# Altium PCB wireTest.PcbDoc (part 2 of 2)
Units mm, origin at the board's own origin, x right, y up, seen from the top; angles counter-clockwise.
Board outline 121.22 x 130.26 mm, 2 copper layers (Top Layer, Bottom Layer); 157 components, 144 nets, 513 pads, 186 vias.
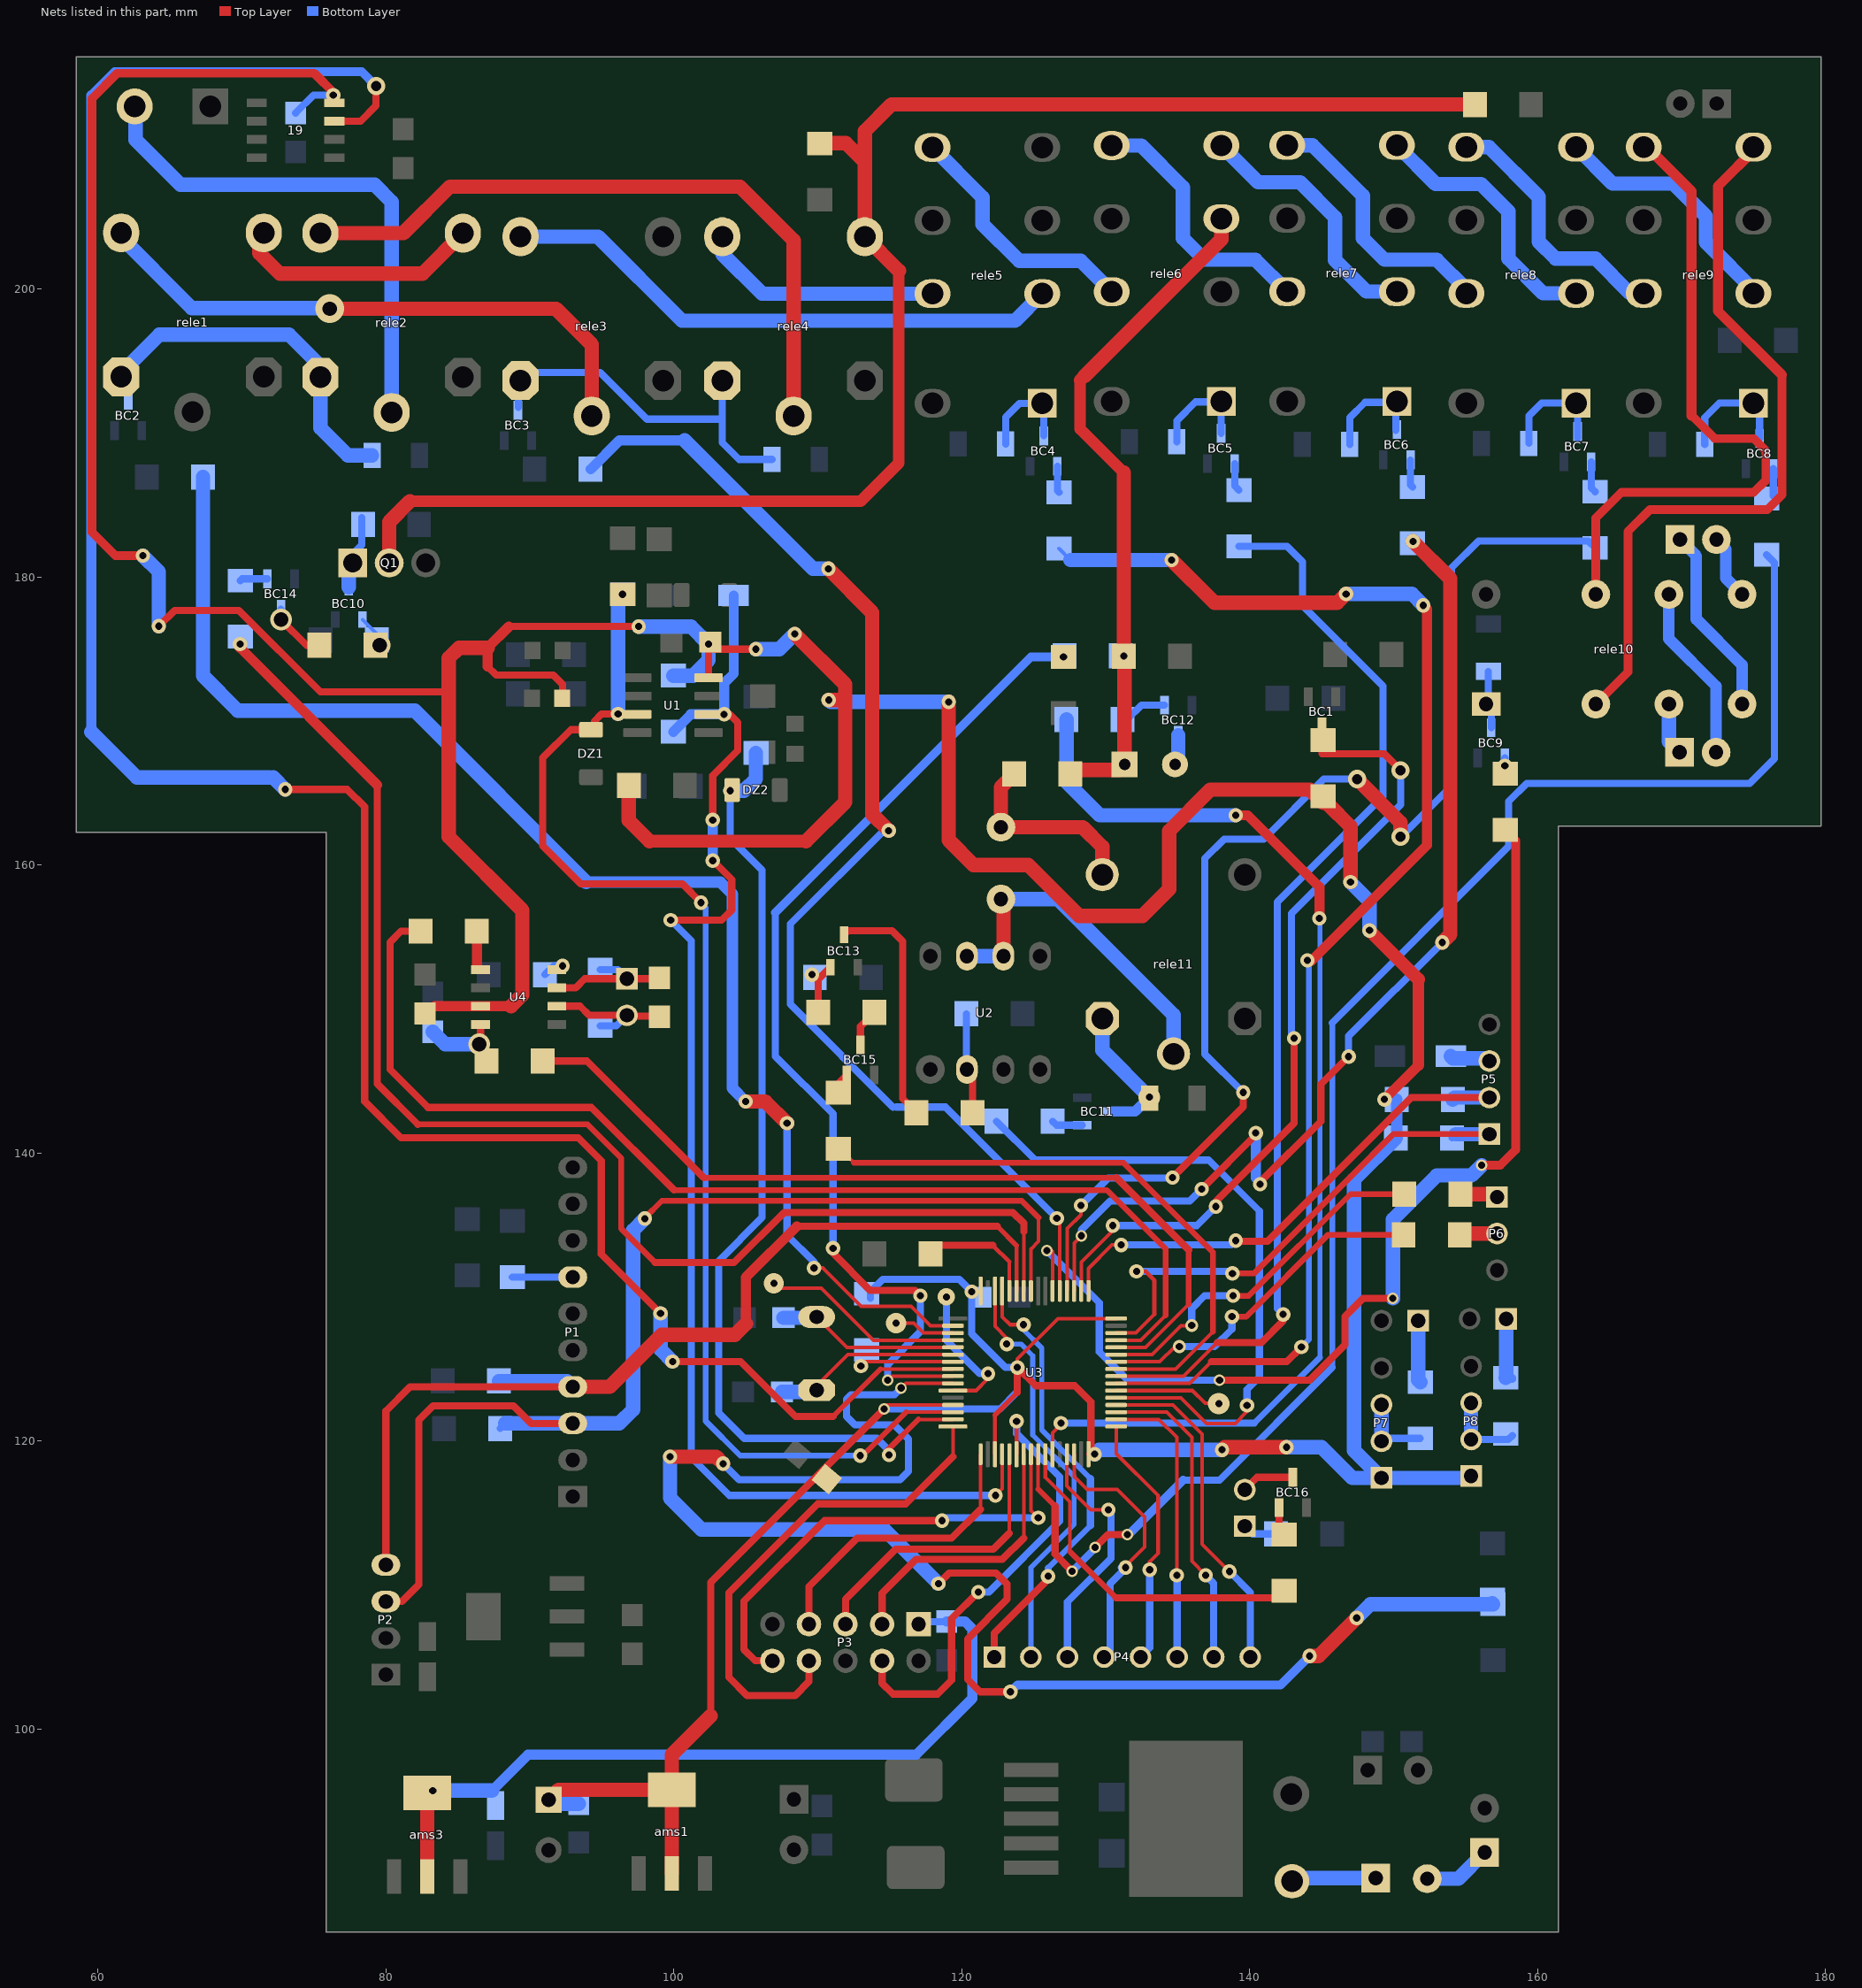
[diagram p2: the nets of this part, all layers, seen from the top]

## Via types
v1: diameter 1, hole 0.5, Top Layer to Bottom Layer, 140 vias
v2: diameter 1.5, hole 1, Top Layer to Bottom Layer, 15 vias
v3: diameter 0.8, hole 0.5, Top Layer to Bottom Layer, 12 vias
v4: diameter 1.27, hole 0.711, Top Layer to Bottom Layer, 6 vias
v5: diameter 2, hole 1, Top Layer to Bottom Layer, 5 vias
v6: diameter 1.5, hole 0.5, Top Layer to Bottom Layer, 3 vias
v7: diameter 1.4, hole 0.5, Top Layer to Bottom Layer, 2 vias
v8: diameter 0.9, hole 0.5, Top Layer to Bottom Layer, 2 vias
v9: diameter 1.2, hole 0.5, Top Layer to Bottom Layer, 1 vias

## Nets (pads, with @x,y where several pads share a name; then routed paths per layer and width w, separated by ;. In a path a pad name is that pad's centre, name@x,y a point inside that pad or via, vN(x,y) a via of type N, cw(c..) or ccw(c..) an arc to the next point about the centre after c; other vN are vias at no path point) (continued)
Net28_1: 28.1 BC4.1 | length 1.9
  Bottom Layer w0.5: BC4.1@126.655,187.697 126.655,185.988 28.1@126.771,185.871
Net29_1: 29.1 BC5.1 | length 2
  Bottom Layer w0.5: BC5.1@138.974,187.875 138.974,186.318 29.1@139.268,186.024
Net30_1: 30.1 BC6.1 | length 1.9
  Bottom Layer w0.5: BC6.1@151.191,188.129 151.191,186.395 30.1@151.333,186.252
Net31_1: 31.1 BC7.1 | length 2.2
  Bottom Layer w0.5: BC7.1@163.739,188.002 163.739,186.191 31.1@164.008,185.922
Net32_1: 32.1 BC8.1 | length 2.2
  Bottom Layer w0.5: BC8.1@176.388,187.52 176.388,185.633 32.1@176.606,185.414
Net33_1: 33.1 BC9.1 | length 0.5
  Bottom Layer w0.5: v1(157.744,166.893) BC9.1@157.744,167.428
Net35_1: 35.1 38.2 BC10.1 | length 2.1
  Top Layer w0.5: 38.2@79.293,175.26 v2(79.578,175.26)
  Bottom Layer w0.25: BC10.1@78.384,177.038 79.369,176.053 35.1@79.369,175.616
Net36_2: 36.2 BC12.1 | length 3.3
  Bottom Layer w0.5: 36.2@131.185,170.104 131.496,170.104 132.495,171.103 BC12.1@134.102,171.103
Net37_1: 37.1 BC11.1 | length 2.2
  Bottom Layer w0.5: 37.1@126.334,142.189 126.598,141.925 BC11.1@128.388,141.925
Net38_1: 38.1 BC14.3 | length 4.1
  Top Layer w0.5: v2(72.72,177.038) 74.498,175.26 38.1@75.393,175.26
  Bottom Layer w0.5: v2(72.72,177.038) BC14.3@72.72,177.766
Net39_1: 39.1 P1.7 | length 4.2
  Bottom Layer w0.5: 39.1@88.798,131.375 92.984,131.375 P1.7@92.989,131.369
Net41_1: 41.1 46.2 BC13.1 | length 3.5
  Top Layer w0.5: 46.2@110.039,149.758 110.039,152.053 BC13.1@110.886,152.901
  other v1: 109.601,152.375
Net42_2: 42.2 48.1 U2.2 | length 7
  Top Layer w0.5: U2.2@120.371,145.798 120.771,145.397 48.1@120.771,142.799
  Bottom Layer w0.5: 42.2@120.326,149.657 120.326,145.843 U2.2@120.371,145.798
Net43_2: 43.2 BC10.3 Q1.1 | length 4.6
  Bottom Layer w0.5: Q1.1@77.699,181.585 78.339,182.225 43.2@78.339,184.125
  Bottom Layer w1: BC10.3@77.434,179.288 77.434,180.711 Q1.1@77.699,180.975
Net45_1: 45.1 BC14.1 | length 1.9
  Bottom Layer w0.5: 45.1@69.901,179.75 70.017,179.866 BC14.1@71.77,179.866
Net46_1: 46.1 BC15.3 | length 2.6
  Top Layer w0.5: BC15.3@112.979,147.506 112.979,148.799 46.1@113.939,149.758
Net47_2: 47.2 BC12.3 | length 2.1
  Bottom Layer w1: 47.2@134.823,166.98 135.052,167.208 BC12.3@135.052,169.003
Net48_2: 48.2 BC13.3 | length 16.8
  Top Layer w0.5: BC13.3@111.836,155.151 112.108,155.423 115.164,155.423 115.9,154.686 115.9,143.77 48.2@116.871,142.799
Net49_2: 49.2 L1.2 rele11.2 | length 13.6
  Top Layer w1: 49.2@123.653,166.319 122.733,165.399 L1.2@122.733,162.622 128.412,162.622 129.775,161.259 rele11.2@129.775,159.327
Net50_1: 50.1 BC15.1 | length 0.9
  Top Layer w0.5: 50.1@111.379,144.756 BC15.1@112.029,145.406
Net53_1: 53.1 ams3.2 ams3.4 C3.1 P3.1 | length 54.8
  Top Layer w1: ams3.2@82.88,89.734 ams3.4@82.88,95.534
  Bottom Layer w0.5: P3.1@117.018,107.264 117.199,107.446 53.1@118.974,107.446
  Bottom Layer w0.7: 87.376,95.707 89.865,98.196 116.84,98.196 120.752,102.108 120.752,106.934 120.24,107.446 53.1@118.974,107.446
  Bottom Layer w1: v1(83.261,95.707) 87.376,95.707
Net54_2: 54.2@156.921,108.655 57.2 U3.10 | length 110.3
  Top Layer w0.25: v3(115.799,123.673) 116.115,123.989 U3.10@119.4,123.989
  Top Layer w0.5: v1(118.389,110.084) 119.126,110.82 122.403,110.82 123.165,110.058 123.165,108.991 120.421,106.248 120.421,103.429 121.285,102.565 v1(123.393,102.565)
  Top Layer w1: v1(99.746,118.897) 102.946,118.897 v1(103.429,118.415) ; v1(144.17,105.054) 144.805,105.054 v1(147.447,107.696)
  Bottom Layer w0.35: v3(115.799,123.673) v3@115.824,123.673
  Bottom Layer w0.5: v1(103.429,118.415) 104.546,117.297 115.722,117.297 116.307,117.881 116.307,120.117 115.316,121.107 112.598,121.107 112.014,121.691 112.014,122.885 112.319,123.19 115.341,123.19 v3@115.824,123.673
  Bottom Layer w0.6: v1(123.393,102.565) 123.876,103.048 142.164,103.048 v1(144.17,105.054)
  Bottom Layer w1: v1(99.746,118.897) 99.746,116.027 101.93,113.843 114.63,113.843 v1(118.389,110.084) ; v1(147.447,107.696) 148.406,108.655 54.2@156.921,108.655 57.2@156.865,108.712
Net55_1: 55.1@113.411,126.32 U3.7 | length 6.7
  Top Layer w0.25: v1(113.005,125.197) 112.928,125.197 113.221,125.489 U3.7@119.4,125.489
Net56_1: 56.1 U3.60 | length 8.2
  Top Layer w0.25: 56.1@117.85,132.994 56.1@118.434,133.579 ; U3.60@123.32,130.409 123.32,132.433
  Top Layer w0.3: 122.174,133.579 123.32,132.433
  Top Layer w0.5: 56.1@118.434,133.579 122.174,133.579
Net60_2: 60.2 U3.5 Y1.2 | length 12.7
  Top Layer w0.25: Y1.2@109.931,128.6 112.042,126.489 U3.5@119.4,126.489
  Bottom Layer w1: 60.2@107.624,128.549 109.88,128.549 Y1.2@109.931,128.6
Net61_2: 61.2 P6.2 | length 2.6
  Top Layer w0.25: 61.2@154.604,134.315 61.2@155.092,134.315
  Top Layer w1: 61.2@155.092,134.315 155.169,134.391 P6.2@157.201,134.391
Net62_2: 62.2 P6.1 | length 2.6
  Top Layer w1: 62.2@154.655,137.135 156.997,137.135 P6.1@157.201,136.931
Net63_1: 63.1 buzzer1.1 | length 2.4
  Bottom Layer w0.5: buzzer1.1@139.67,114.071 140.203,113.538 63.1@141.834,113.538
Net64_2: 64.2 U3.6 Y1.1 | length 13.1
  Top Layer w0.25: Y1.1@109.931,123.52 109.931,123.825 112.096,125.989 U3.6@119.4,125.989
  Bottom Layer w1: 64.2@107.522,123.393 109.804,123.393 Y1.1@109.931,123.52
Net66_1: 66.1 BC16.1 | length 2
  Top Layer w0.5: BC16.1@142.062,115.367 142.062,113.837 66.1@142.418,113.481
Net68_1: 68.1 led1.1 | length 4.3
  Bottom Layer w1: led1.1@151.714,128.346 151.714,124.226 68.1@151.867,124.073
Net68_2: 68.2 P7.2 P7.3 | length 5.3
  Bottom Layer w0.5: P7.2@149.174,119.964 149.383,120.173 68.2@151.867,120.173
  Bottom Layer w1: P7.2@149.174,119.964 P7.3@149.174,122.504
Net69_1: 69.1 led2.1 | length 4.2
  Bottom Layer w0.5: 69.1@158.267,124.276 69.1@158.267,124.378
  Bottom Layer w1: 69.1@157.81,124.378 157.836,124.403 led2.1@157.836,128.473
Net69_2: 69.2 P8.2 P8.3 | length 5.5
  Bottom Layer w0.5: P8.2@155.397,120.091 157.982,120.091 69.2@158.267,120.376
  Bottom Layer w1: P8.2@155.397,120.091 P8.3@155.397,122.631
Net71_1: 71.1 73.1 U4.4 | length 6.3
  Top Layer w0.5: v2(86.487,147.549) 86.487,146.894 73.1@87.001,146.38 ; v2@86.58,147.549 U4.4@86.58,148.92
  Bottom Layer w1: 71.1@83.261,148.408 84.121,147.549 v2(86.487,147.549)
Net72_1: 72.1 U4.1 | length 2.8
  Top Layer w0.5: U4.1@86.329,152.982 U4.1@86.58,152.73
  Top Layer w0.7: U4.1@86.329,152.982 72.1@86.329,155.397
Net74_1: 74.1 75.2 buzzer2.1 U4.7 | length 9.6
  Top Layer w0.5: U4.7@91.88,151.46 93.193,151.46 93.828,152.095 buzzer2.1@96.749,152.095 98.955,152.095 75.2@99.06,152.201
  Bottom Layer w0.5: 74.1@94.894,152.724 96.119,152.724 buzzer2.1@96.749,152.095
Net74_2: 74.2 75.1 buzzer2.2 U4.6 | length 9.6
  Top Layer w0.5: U4.6@91.88,150.19 93.497,150.19 94.132,149.555 buzzer2.2@96.749,149.555 96.803,149.501 75.1@99.06,149.501
  Bottom Layer w0.5: 74.2@94.894,148.824 96.018,148.824 buzzer2.2@96.749,149.555
Net76_1: 76.1 U4.8 | length 1.5
  Bottom Layer w0.5: 76.1@91.053,152.375 91.663,152.984 v1(92.278,152.984)
NetBC2_3: BC2.3 D5.1 rele1.4 rele2.4 | length 25.6
  Bottom Layer w0.5: rele1.4@61.322,193.208 rele1.4@61.322,193.878
  Bottom Layer w1: rele1.4@61.322,193.878 64.268,196.825 73.279,196.825 75.463,194.64 rele2.4@75.463,193.878 75.463,190.348 77.368,188.443 D5.1@79.045,188.443
NetBC3_3: BC3.3 D6.1 rele3.4 rele4.4 | length 25.8
  Bottom Layer w0.5: BC3.3@89.205,191.772 89.205,193.48 rele3.4@89.36,193.636 89.933,194.208 94.894,194.208 98.146,190.957 103.378,190.957 ; rele4.4@103.378,193.632 103.378,189.332 104.546,188.163 D6.1@106.832,188.163
NetBC4_3: BC4.3 D7.1 rele5.1 | length 7.1
  Bottom Layer w0.5: D7.1@123.061,189.23 123.061,191.108 124.011,192.058 rele5.1@125.603,192.058 125.705,191.956 BC4.3@125.705,189.797
NetBC5_3: BC5.3 D8.1 rele6.1 | length 7.3
  Bottom Layer w0.5: D8.1@134.95,189.382 134.95,190.856 136.254,192.159 rele6.1@138.024,192.159 ; BC5.3@138.024,189.975 rele6.1@138.024,192.159 ; rele6.1@138.049,192.185 rele6.1@138.024,192.159
NetBC6_3: BC6.3 D9.1 rele7.1 | length 7.5
  Bottom Layer w0.5: D9.1@146.964,189.205 146.964,191.059 148.031,192.126 rele7.1@150.165,192.126 ; BC6.3@150.165,190.195 rele7.1@150.165,192.126 ; rele7.1@150.241,192.202 rele7.1@150.165,192.126
NetBC7_3: BC7.3 D10.1 rele8.1 | length 8
  Bottom Layer w0.5: D10.1@159.41,189.281 159.41,191.186 160.299,192.075 rele8.1@162.687,192.075 162.789,191.973 BC7.3@162.789,189.645
NetBC8_3: BC8.3 D11.1 rele9.1 | length 8.4
  Bottom Layer w0.5: D11.1@171.628,189.205 171.628,191.059 172.644,192.075 175.26,192.075 175.438,191.897 BC8.3@175.438,189.62
NetBC9_3: BC9.3 D12.1 rele10.1 | length 4.1
  Bottom Layer w0.5: D12.1@156.591,173.433 156.591,171.323 rele10.1@156.439,171.171 156.794,170.815 BC9.3@156.794,169.528
NetBC11_3: BC11.3 D13.1 rele11.4 | length 9.8
  Bottom Layer w0.7: BC11.3@130.488,142.875 132.055,142.875 v6(133.045,143.866)
  Bottom Layer w1: rele11.4@129.775,149.327 129.775,147.136 v6(133.045,143.866)
NetBC16_3: BC16.3 buzzer1.2 | length 3.7
  Top Layer w0.5: buzzer1.2@139.67,116.611 140.525,117.467 BC16.3@143.012,117.467
NetD14_A: D14.A P5.3 | length 2.8
  Bottom Layer w1: D14.A@153.982,146.71 154.134,146.558 156.489,146.558 P5.3@156.667,146.38
NetDin1_1: Din1.1 Inbutton1.1 | length 5.9
  Bottom Layer w1: Din1.1@142.951,89.408 143.18,89.637 Inbutton1.1@148.768,89.637
NetIn+1_1: In+1.1 Inbutton1.2 | length 4.7
  Bottom Layer w1: Inbutton1.2@152.349,89.586 154.508,89.586 In+1.1@156.337,91.415
NetInbutton3_1: Inbutton3.1 rele10.8 | length 13.2
  Bottom Layer w0.8: Inbutton3.1@169.901,182.601 171.044,181.458 171.044,177.063 174.219,173.888 rele10.8@174.219,171.171
NetInbutton3_2: Inbutton3.2 rele10.9 | length 4.5
  Bottom Layer w0.8: Inbutton3.2@172.441,182.601 173.101,181.94 173.101,179.908 rele10.9@174.219,178.791
NetInbutton4_1: Inbutton4.1 rele10.6 | length 3.7
  Bottom Layer w1: rele10.6@169.139,171.171 169.139,168.554 Inbutton4.1@169.875,167.818
NetInbutton4_2: Inbutton4.2 rele10.11 | length 12.3
  Bottom Layer w0.8: rele10.11@169.139,178.791 169.139,175.692 172.415,172.415 Inbutton4.2@172.415,167.818
NetL1_1: L1.1 rele11.1 U2.6 U2.7 | length 24.6
  Top Layer w1: L1.1@122.733,157.622 122.911,157.444 U2.6@122.911,153.668
  Bottom Layer w1: U2.7@120.371,153.668 U2.6@122.911,153.668 ; L1.1@122.733,157.622 126.681,157.622 134.725,149.578 rele11.1@134.725,146.877
NetpinIN1_2: pinIN1.2 rele2.1 | length 36.8
  Bottom Layer w1: pinIN1.2@62.078,212.7 62.611,212.166 62.611,210.363 65.735,207.239 79.223,207.239 80.413,206.048 rele2.1@80.413,191.428
Netrele1_2: rele1.2 rele3.1 | length 41
  Top Layer w1: v5(76.098,198.628) 91.821,198.628 94.31,196.139 rele3.1@94.31,191.186
  Bottom Layer w1: rele1.2@61.322,203.878 66.521,198.679 v5@75.946,198.679
Netrele1_3: rele1.3 rele2.3 | length 17.3
  Top Layer w1: rele1.3@71.222,203.878 71.222,202.489 72.644,201.066 82.552,201.066 rele2.3@85.363,203.878
Netrele2_2: rele2.2 rele4.1 | length 47.9
  Top Layer w1: rele2.2@75.463,203.878 81.222,203.878 84.455,207.112 104.597,207.112 108.328,203.381 rele4.1@108.328,191.182
Netrele3_2: rele3.2 rele5.4 | length 39.4
  Bottom Layer w1: rele3.2@89.36,203.636 94.738,203.636 100.584,197.79 123.715,197.79 rele5.4@125.603,199.678
Netrele4_2: rele4.2 rele5.13 | length 16.9
  Bottom Layer w1: rele4.2@103.378,203.632 103.378,202.438 106.138,199.678 rele5.13@117.983,199.678
Netrele5_9: rele5.9 rele6.13 | length 17.7
  Bottom Layer w1: rele5.9@117.983,209.838 121.463,206.358 121.463,204.495 124.003,201.955 128.278,201.955 rele6.13@130.429,199.805
Netrele6_8: rele6.8 rele7.4 | length 18.1
  Bottom Layer w1: rele6.8@138.049,209.965 140.597,207.416 143.51,207.416 145.948,204.978 145.948,202.006 148.133,199.822 rele7.4@150.241,199.822
Netrele6_9: rele6.9 rele7.13 | length 18.5
  Bottom Layer w1: rele6.9@130.429,209.965 132.478,209.965 135.382,207.061 135.382,203.53 136.881,202.032 140.411,202.032 rele7.13@142.621,199.822
Netrele7_8: rele7.8 rele8.4 | length 18.6
  Bottom Layer w1: rele7.8@150.241,209.982 152.933,207.289 156.083,207.289 157.988,205.384 157.988,202.108 160.401,199.695 rele8.4@162.687,199.695
Netrele7_9: rele7.9 rele8.13 | length 18.6
  Bottom Layer w1: rele7.9@142.621,209.982 144.374,209.982 147.879,206.477 147.879,203.53 149.377,202.032 153.01,202.032 155.067,199.974 rele8.13@155.067,199.695
Netrele8_8: rele8.8 rele9.4 | length 17.8
  Bottom Layer w1: rele8.8@162.687,209.855 165.227,207.315 169.443,207.315 171.704,205.054 171.704,203.251 rele9.4@175.26,199.695
Netrele8_9: rele8.9 rele9.13 | length 18.6
  Bottom Layer w1: rele8.9@155.067,209.855 156.642,209.855 160.096,206.4 160.096,203.276 161.265,202.108 164.033,202.108 166.446,199.695 rele9.13@167.64,199.695
Netrele9_8: rele9.8 rele10.4 | length 51.8
  Top Layer w0.6: rele10.4@164.059,171.171 166.294,173.406 166.294,183.159 167.818,184.683 175.971,184.683 176.987,185.699 176.987,194.031
  Top Layer w0.7: rele9.8@175.26,209.855 172.542,207.137 172.542,198.476 176.987,194.031
Netrele9_9: rele9.9 rele10.13 | length 46.3
  Top Layer w0.6: rele10.13@164.059,178.791 164.059,184.099 165.837,185.877 175.031,185.877 175.87,186.715 175.87,188.773 175.031,189.611 172.314,189.611 170.713,191.211
  Top Layer w0.7: rele9.9@167.64,209.855 170.713,206.781 170.713,191.211
NetU3_3: U3.3 | length 4.2
  Top Layer w0.25: v7(115.443,128.168) 116.688,128.168 117.367,127.489 U3.3@119.4,127.489
NetU3_4: U3.4 | length 14.1
  Top Layer w0.25: v7(106.959,130.937) 107.29,130.607 110.261,130.607 113.879,126.989 U3.4@119.4,126.989
NetU3_11: U3.11 | length 10
  Top Layer w0.25: U3.11@119.4,123.489 121,123.489 121.844,124.333 v1(121.844,124.663)
  Bottom Layer w0.5: v9(118.948,129.997) 118.948,126.975 121.26,124.663 v1(121.844,124.663)
NetU3_38: U3.38 | length 7.5
  Top Layer w0.25: U3.38@130.74,123.489 136.048,123.489 136.931,122.606 137.871,122.606 v6(137.871,122.58)
outSelonoeid: 24.2 25.1 Q1.2 rele4.3 | length 110.6
  Top Layer w0.8: 81.686,185.268 113.005,185.268 115.646,187.909 115.646,201.264
  Top Layer w1: Q1.2@80.239,180.975 80.239,183.82 81.686,185.268 ; 25.1@110.134,210.103 110.166,210.134 111.963,210.134 113.278,208.819 ; 115.646,201.264 rele4.3@113.278,203.632 113.278,208.819 ; 24.2@155.397,212.827 115.138,212.827 113.278,210.966 113.278,208.819
outSimulation+5: 44.2 47.1 49.1 51.1 rele6.6 | length 47.3
  Top Layer w0.8: 128.245,193.65 128.245,190.271 131.273,187.243
  Top Layer w0.9: 128.245,193.65 128.549,193.954
  Top Layer w1: 49.1@127.553,166.319 127.832,166.599 130.942,166.599 47.1@131.323,166.98 131.323,174.448 v1(131.273,174.498) 131.273,187.243 ; 128.549,193.954 138.049,203.454 rele6.6@138.049,204.885
pa0: 11.2 13.1 DZ1.2 U1.3 U3.14 | length 89.6
  Top Layer w0.25: DZ1.2@94.259,169.392 DZ1.2@94.488,169.392 ; v1(112.954,118.974) v1@113.132,118.974 ; 116.147,121.989 U3.14@119.4,121.989
  Top Layer w0.4: v1@113.132,118.974 116.147,121.989
  Top Layer w0.5: DZ1.2@94.259,169.392 92.861,169.392 90.907,167.437 90.907,161.315 93.548,158.674 100.609,158.674 v1(101.905,157.378) ; DZ1.2@94.488,169.392 94.488,169.977 94.996,170.485 v1(96.139,170.485)
  Bottom Layer w0.25: v1(101.905,157.378) v1@102.235,157.048
  Bottom Layer w0.4: v1@102.235,157.048 102.235,121.361 104.623,118.974 v1(112.954,118.974)
  Bottom Layer w1: v1(96.139,170.485) 96.139,178.492 v1(96.444,178.796)
pa1: 15.2 DZ2.2 U3.15 | length 68.6
  Top Layer w0.25: v1@114.833,119.329 115.138,119.024 v1(114.96,119.024) ; 116.994,121.489 U3.15@119.4,121.489
  Top Layer w0.4: v1@114.833,119.329 116.994,121.489
  Bottom Layer w0.5: v1(103.937,165.151) 103.937,161.849 106.147,159.639 106.147,135.509 103.124,132.486 103.124,121.945 104.902,120.167 114.122,120.167 114.96,119.329 v1(114.96,119.024)
  Bottom Layer w1: v1(103.937,165.151) 104.877,165.151 105.715,165.989 15.2@105.715,167.773
pa2: P3.8 U3.16 | length 35.4
  Top Layer w0.25: 119.4,118.892 U3.16@119.4,120.989
  Top Layer w0.5: P3.8@109.398,104.724 109.398,103.276 108.433,102.311 105.105,102.311 103.835,103.581 103.835,109.449 110.007,115.621 116.129,115.621 119.4,118.892
pa3: P3.7 U3.17 | length 20.6
  Top Layer w0.25: 121.32,115.249 U3.17@121.32,119.069
  Top Layer w0.5: P3.7@109.398,107.264 109.398,109.88 112.751,113.233 119.304,113.233 121.32,115.249
pa4: 23.2 D3.A U1.6 U3.20 | length 95.8
  Top Layer w0.25: v1(122.352,116.205) 122.82,116.673 U3.20@122.82,119.069
  Top Layer w0.5: v1(99.797,156.159) 103.327,156.159 104.038,156.87 104.038,158.979 v1(102.718,160.299) ; v1(102.718,163.119) 102.718,166.218 104.445,167.945 104.445,169.901 103.886,170.459 v1(103.505,170.459)
  Bottom Layer w0.5: v1(99.797,156.159) 101.219,154.737 101.219,118.847 103.861,116.205 v1(122.352,116.205)
  Bottom Layer w0.7: 23.2@99.974,169.246 101.188,170.459 v1(103.505,170.459) 103.505,172.618 104.172,173.286 D3.A@104.172,178.714 ; v1(102.718,160.299) v1(102.718,163.119)
pa5: P3.5 U3.21 | length 20.5
  Top Layer w0.25: 123.32,113.591 U3.21@123.32,119.069
  Top Layer w0.5: P3.5@111.938,107.264 111.938,108.991 115.418,112.471 122.199,112.471 123.32,113.591
pa6: P3.4 U3.22 | length 32.2
  Top Layer w0.25: U3.22@123.82,119.069 123.82,121.356 v1(123.825,121.361)
  Top Layer w0.5: P3.4@114.478,104.724 114.478,103.175 115.24,102.413 118.339,102.413 119.304,103.378 119.304,107.645 v1(121.158,109.499)
  Bottom Layer w0.5: v1(121.158,109.499) 121.895,109.499 126.822,114.427 126.822,117.5 123.825,120.498 v1(123.825,121.361)
pa7: P3.3 U3.23 | length 19.4
  Top Layer w0.25: 124.32,113.245 U3.23@124.32,119.069
  Top Layer w0.5: P3.3@114.478,107.264 114.478,109.398 116.84,111.76 122.834,111.76 124.32,113.245
pa8: 50.2 U3.41 | length 42.1
  Top Layer w0.25: 50.2@111.379,139.604 112.237,139.604 112.522,139.319 ; U3.41@130.74,124.989 134.87,124.989 137.465,127.584
  Top Layer w0.4: 112.522,139.319 131.242,139.319 137.465,133.096 137.465,127.584
pa9: 61.1 U3.42 | length 24.1
  Top Layer w0.25: U3.42@130.74,125.489 133.77,125.489 134.823,126.543 v8(135.128,126.543)
  Top Layer w0.4: v1(138.786,128.626) 139.776,128.626 145.466,134.315 61.1@150.704,134.315
  Bottom Layer w0.5: v8(135.128,126.543) 137.566,126.543 138.786,127.762 v1(138.786,128.626)
pa10: 62.1 U3.43 | length 25.3
  Top Layer w0.25: U3.43@130.74,125.989 133.228,125.989 135.23,127.991 135.966,127.991 v8(135.992,128.016)
  Top Layer w0.4: v1(138.862,130.073) 139.954,130.073 147.015,137.135 62.1@150.755,137.135
  Bottom Layer w0.5: v8(135.992,128.016) 135.992,129.184 136.881,130.073 v1(138.862,130.073)
pa11: 73.2 U3.44 | length 60.4
  Top Layer w0.25: U3.44@130.74,126.489 132.789,126.489 135.788,129.489
  Top Layer w0.4: 102.083,138.278 130.759,138.278 ; 135.788,129.489 135.788,133.248
  Top Layer w0.5: 73.2@90.901,146.38 93.98,146.38 102.083,138.278 ; 130.759,138.278 135.788,133.248
pa12: 72.2 U3.45 | length 79.1
  Top Layer w0.25: U3.45@130.74,126.989 132.45,126.989 134.188,128.727
  Top Layer w0.4: 100.025,137.414 130.099,137.414 134.188,133.325 134.188,128.727
  Top Layer w0.5: 72.2@82.429,155.397 81.051,155.397 80.289,154.635 80.289,145.796 82.931,143.154 94.285,143.154 100.025,137.414
pa13: 59.2 P5.1 U3.46 | length 38.3
  Top Layer w0.25: U3.46@130.74,127.489 132.112,127.489 133.401,128.778 ; v1(132.156,131.775) 132.766,131.775
  Top Layer w0.3: 132.766,131.775 133.401,131.14 133.401,128.778
  Top Layer w0.4: v1(138.811,131.623) 140.31,131.623 149.987,141.3 P5.1@156.667,141.3
  Bottom Layer w0.5: v1(132.156,131.775) 138.659,131.775 v1(138.811,131.623) ; 59.2@154.071,141.046 59.2@154.325,141.3
  Bottom Layer w1: 59.2@154.325,141.3 P5.1@156.667,141.3
pa14: 58.2 P5.2 U3.49 | length 37
  Top Layer w0.25: U3.49@128.82,130.409 128.82,131.969 130.454,133.604 v1(131.089,133.604)
  Top Layer w0.5: v1(139.04,133.909) 139.09,133.858 141.249,133.858 151.232,143.84 P5.2@156.667,143.84
  Bottom Layer w0.25: v1@131.064,133.604 v1(131.089,133.604)
  Bottom Layer w0.5: v1(131.089,133.604) 138.735,133.604 v1(139.04,133.909)
  Bottom Layer w1: 58.2@154.121,143.713 154.248,143.84 P5.2@156.667,143.84
pa15: 9.1 BC1.3 U3.50 | length 56.7
  Top Layer w0.25: U3.50@128.32,130.409 128.32,132.409 130.505,134.595 v1(130.505,134.95)
  Top Layer w0.5: v1(137.668,136.271) 137.668,136.627 143.104,142.062 v1(143.104,147.955) ; BC1.3@145.034,169.587 145.034,167.736 145.059,167.71 149.358,167.71 v4(150.495,166.573)
  Bottom Layer w0.5: v1(130.505,134.95) 136.347,134.95 v1(137.668,136.271) ; v1(143.104,147.955) 142.926,148.133 142.926,156.616 150.495,164.186 v4(150.495,166.573)
pb0: 66.2 U3.26 | length 23.9
  Top Layer w0.25: U3.26@125.82,119.069 125.82,117.462 127.533,115.748 127.533,112.293
  Top Layer w0.4: 127.533,112.293 130.734,109.093
  Top Layer w0.5: 130.734,109.093 141.929,109.093 66.2@142.418,109.581
pb1: 36.1 U3.27 | length 80.6
  Top Layer w0.25: U3.27@126.32,119.069 126.32,120.554 126.898,121.133 v1(126.898,121.234)
  Top Layer w0.7: v1(139.04,163.449) 139.878,163.449 144.856,158.471 v1(144.856,156.286)
  Bottom Layer w0.25: v1(144.856,156.286) 144.856,156.566 v1@144.907,156.616
  Bottom Layer w0.35: 144.907,125.806 v1@144.907,156.616
  Bottom Layer w0.4: 140.335,121.234 144.907,125.806
  Bottom Layer w0.5: v1(126.898,121.234) 140.335,121.234
  Bottom Layer w1: 36.1@127.285,170.104 127.285,165.755 129.591,163.449 v1(139.04,163.449)
pb6: 45.2 U3.58 | length 93.9
  Top Layer w0.25: v1@69.875,175.082 v1(69.875,175.336) ; U3.58@124.32,130.409 124.32,134.53
  Top Layer w0.4: 82.22,141.986 94.005,141.986 96.368,139.624 96.368,134.722 98.704,132.385
  Top Layer w0.5: 79.4,165.557 79.4,144.805 82.22,141.986 ; 98.704,132.385 104.191,132.385 107.671,135.865 123.571,135.865 124.32,135.116 124.32,134.53
  Top Layer w0.7: v1@69.875,175.082 79.4,165.557
pb8: P4.1 U3.61 | length 31.5
  Top Layer w0.25: U3.61@122.82,130.409 122.82,128.615 123.368,128.067 v1(124.308,128.067) ; v1(126.009,110.592) v1@126.187,110.592
  Top Layer w0.5: P4.1@122.276,104.978 122.276,106.629 126.027,110.381 v1(126.009,110.592)
  Bottom Layer w0.25: v1@124.308,127.711 v1(124.308,128.067)
  Bottom Layer w0.35: v1@124.308,127.711 125.578,126.441 125.578,120.752 128.956,117.373
  Bottom Layer w0.4: 126.009,111.15 128.956,114.097
  Bottom Layer w0.5: v1(126.009,110.592) 126.009,111.15 ; 128.956,114.097 128.956,117.373
pb9: P4.2 U3.62 | length 29.5
  Top Layer w0.25: U3.62@122.32,130.409 122.32,127.947 123.139,127.127 v1(123.139,126.721)
  Bottom Layer w0.35: v1(123.139,126.721) 124.13,126.721 124.943,125.908 124.943,120.396 127.813,117.526 127.813,114.198 124.816,111.201 P4.2@124.816,104.978
pb10: P4.3 U3.29 | length 17.3
  Top Layer w0.25: U3.29@127.32,119.069 127.32,116.876 128.981,115.214 v1(130.2,115.214)
  Bottom Layer w0.25: v1(130.2,115.214) v1@130.378,115.037
  Bottom Layer w0.5: P4.3@127.356,104.978 127.356,108.814 130.378,111.836 v1@130.378,115.037
pb11: P4.4 U3.30 | length 19
  Top Layer w0.25: U3.30@127.82,119.069 127.82,117.519 128.727,116.611 130.81,116.611 132.715,114.706 132.715,112.624 131.293,111.201 v1(131.394,111.201)
  Bottom Layer w0.5: P4.4@129.896,104.978 130.327,105.41 130.327,110.084 131.267,111.023 131.089,111.201 v1(131.394,111.201)
pb12: P4.5 U3.33 | length 17.7
  Top Layer w0.25: U3.33@130.74,120.989 130.74,119.095 133.655,116.18 133.655,112.192 133.071,111.608 v1(133.071,111.049)
  Bottom Layer w0.5: P4.5@132.436,104.978 133.071,105.613 v1(133.071,111.049)
pb13: P4.6 U3.34 | length 20
  Top Layer w0.25: U3.34@130.74,121.489 133.704,121.489 134.95,120.244 v1(134.95,110.668)
  Bottom Layer w0.5: v1(134.95,110.668) 134.976,110.642 P4.6@134.976,104.978
pb14: P4.7 U3.35 | length 21.9
  Top Layer w0.25: U3.35@130.74,121.989 134.246,121.989 135.992,120.244 135.992,111.633 v1(136.957,110.668)
  Bottom Layer w0.5: v1(136.957,110.668) 137.516,110.109 P4.7@137.516,104.978
pb15: P4.8 U3.36 | length 23.7
  Top Layer w0.25: U3.36@130.74,122.489 134.686,122.489 136.703,120.472 136.703,112.827 v1(138.608,110.922)
  Bottom Layer w0.5: v1(138.608,110.922) 140.056,109.474 P4.8@140.056,104.978
pc0: 19.7 U3.8 | length 168
  Top Layer w0.25: 114.372,124.989 U3.8@119.4,124.989
  Top Layer w0.35: 111.074,121.691 114.372,124.989
  Top Layer w0.5: v1(73.012,165.24) 77.33,165.24 78.537,164.033 78.537,143.561 81.051,141.046 93.37,141.046 94.971,139.446 94.971,132.969 v1(99.085,128.854) ; 19.7@76.436,211.658 78.257,211.658 79.324,212.725 v4(79.324,214.097) ; v1(99.924,125.501) 104.648,125.501 108.458,121.691 111.074,121.691
  Bottom Layer w0.5: 71.907,166.065 72.187,166.065
  Bottom Layer w0.6: 59.538,213.462 61.163,215.087 78.334,215.087 v4(79.324,214.097)
  Bottom Layer w0.7: 59.538,169.24 59.538,213.462
  Bottom Layer w1: 59.538,169.24 62.713,166.065 71.907,166.065 ; 72.187,166.065 v1(73.012,165.24) ; v1(99.085,128.854) 99.085,126.34 v1(99.924,125.501)
pc1: 51.2 52.2 U3.9 | length 71.5
  Top Layer w0.25: v3(114.859,124.206) 115.142,124.489 U3.9@119.4,124.489
  Top Layer w0.5: v1(111.074,133.375) 111.074,133.02 113.64,130.454 116.764,130.454 v1(117.145,130.073) ; 52.2@127.057,174.467 v1(127.076,174.447)
  Bottom Layer w0.5: 107.061,156.693 107.061,146.71 111.074,142.697 v1(111.074,133.375) ; v3(114.859,124.206) 114.859,125.298 117.145,127.584 v1(117.145,130.073)
  Bottom Layer w0.6: 107.061,156.693 124.816,174.447 v1(127.076,174.447)
pc4: P3.10 U3.24 | length 33.1
  Top Layer w0.25: U3.24@124.82,119.069 124.82,115.16 v1(125.324,114.656)
  Top Layer w0.5: P3.10@106.858,104.724 105.664,104.724 104.877,105.512 104.877,108.864 110.465,114.452 v1(118.643,114.452)
  Bottom Layer w0.5: v1(118.643,114.452) 118.847,114.656 v1(125.324,114.656)
pc5: 32.2 U3.25 | length 111.5
  Top Layer w0.25: 125.32,116.637 U3.25@125.32,119.069
  Top Layer w0.4: 125.32,116.637 126.488,115.468
  Top Layer w0.5: 126.488,115.468 126.492,115.468 126.492,112.141 v3(127.686,110.947) ; v3(129.286,112.598) 130.175,113.487 v3(131.521,113.487)
  Bottom Layer w0.25: 145.745,148.869 145.745,149.022
  Bottom Layer w0.4: 145.745,125.095 145.745,148.869
  Bottom Layer w0.5: v3(127.686,110.947) 129.286,112.547 v3(129.286,112.598) ; v3(131.521,113.487) v3@131.597,113.487 ; 135.382,117.272 137.922,117.272 145.745,125.095 ; 145.745,149.022 158.013,161.29 158.013,164.414 159.258,165.659 174.752,165.659 176.479,167.386 176.479,180.981 32.2@175.92,181.54
  Bottom Layer w0.6: v3@131.597,113.487 135.382,117.272
pc6: 37.2 U3.37 | length 45.3
  Top Layer w0.25: U3.37@130.74,122.989 135.227,122.989 137.008,121.209 139.014,121.209 139.827,122.022 v1(139.827,122.453)
  Bottom Layer w0.5: 37.2@122.434,142.189 125.126,139.497 137.16,139.497 140.691,135.966 140.691,124.435 139.827,123.571 v1(139.827,122.453)
pc8: 28.2 U3.39 | length 96.9
  Top Layer w0.25: U3.39@130.74,123.989 135.851,123.989 137.363,125.501
  Top Layer w0.5: 137.363,125.501 142.596,125.501 v1(143.612,126.517) ; v1(144.018,153.365) v1@144.323,153.365 ; v1(152.07,178.029) v1@152.324,177.775
  Top Layer w0.7: v1@144.323,153.365 152.324,161.366 v1@152.324,177.775
  Top Layer w1: v1(134.595,181.178) 137.566,178.206 146.101,178.206 v1(146.71,178.816)
  Bottom Layer w0.25: 28.2@126.771,181.971 28.2@127.565,181.178 ; v1(144.018,153.365) v1@144.141,153.242
  Bottom Layer w0.4: v1(143.612,126.517) 144.141,127.047 v1@144.141,153.242
  Bottom Layer w1: 28.2@127.565,181.178 v1(134.595,181.178) ; v1(146.71,178.816) 151.282,178.816 v1(152.07,178.029)
pc9: 29.2 U3.40 | length 76.3
  Top Layer w0.25: U3.40@130.74,124.489 135.411,124.489 137.744,126.822
  Top Layer w0.5: 137.744,126.822 140.842,126.822 142.342,128.322 v1(142.342,128.778)
  Bottom Layer w0.5: 29.2@139.268,182.124 142.615,182.124 143.688,181.051 143.688,178.003 149.276,172.415 149.276,164.77 141.935,157.429 141.935,129.184 v1(142.342,128.778)
pc10: 30.2 U3.51 | length 74.3
  Top Layer w0.25: U3.51@127.82,130.409 127.82,133.738 v3(128.321,134.239)
  Top Layer w0.5: v1(136.677,137.49) 140.437,141.249 v1(140.437,141.376) ; v1(140.741,137.82) 140.741,137.973 144.958,142.189 144.958,144.755 v1(146.888,146.685)
  Top Layer w1: v1(151.359,182.474) 153.949,179.883 153.949,155.169 v1(153.391,154.61)
  Bottom Layer w0.5: v3(128.321,134.239) 128.321,134.645 130.327,136.652 135.839,136.652 v1(136.677,137.49) ; 140.437,138.252 140.741,137.947 v1(140.741,137.82) ; v1(146.888,146.685) 146.888,148.107 v1(153.391,154.61)
  Bottom Layer w0.7: 140.437,138.252 v1(140.437,141.376)
pc11: 31.2 U3.52 | length 88
  Top Layer w0.25: U3.52@127.32,130.409 127.346,130.436 127.346,134.738 128.295,135.687 v1(128.295,136.347)
  Top Layer w0.5: v1(134.645,138.278) 139.573,143.205 v1(139.573,144.196)
  Top Layer w1: v4(147.472,165.964) 150.495,162.941 v4(150.495,161.95)
  Bottom Layer w0.5: v1(128.295,136.347) 130.2,138.252 134.62,138.252 v1(134.645,138.278) ; v1(139.573,144.196) 136.906,146.863 136.906,160.452 138.252,161.798 140.995,161.798 145.161,165.964 v4(147.472,165.964) ; v4(150.495,161.95) 154.026,165.481 154.026,180.619 155.905,182.499 163.531,182.499 31.2@164.008,182.022
pc12: 27.2 U3.53 | length 85.9
  Top Layer w0.25: v1(126.619,135.458) 126.82,135.258 U3.53@126.82,130.409
  Top Layer w1: v1(110.744,180.569) 113.792,177.521 113.792,163.525 v1(114.935,162.382)
  Bottom Layer w0.25: 115.24,143.18 115.468,143.18
  Bottom Layer w0.5: v1(114.935,162.382) 114.579,162.382 108.102,155.905 108.102,150.317 115.24,143.18 ; 115.468,143.18 118.897,143.18 v1(126.619,135.458)
  Bottom Layer w0.7: 27.2@94.228,187.477 96.235,189.484 100.762,189.484
  Bottom Layer w1: 100.762,189.484 109.677,180.569 v1(110.744,180.569)
pc13: 26.2 U3.2 | length 97.3
  Top Layer w0.25: v1(109.753,132.004) 110.363,132.004 113.03,129.337 116.484,129.337 117.832,127.989 U3.2@119.4,127.989
  Top Layer w1: v1(105.004,143.561) 106.375,143.561 v1(107.874,142.062)
  Bottom Layer w0.5: v1(107.874,142.062) 107.874,134.29 109.753,132.41 v1(109.753,132.004)
  Bottom Layer w0.8: 93.929,158.801 103.251,158.801 104.089,157.963 104.089,144.475 v1(105.004,143.561)
  Bottom Layer w1: 26.2@67.304,186.944 67.304,173.132 69.723,170.713 82.017,170.713 93.929,158.801
pd2: 33.2 U3.54 | length 75.1
  Top Layer w0.25: v3(125.933,133.223) 126.035,133.223 126.136,133.325 126.32,133.141 U3.54@126.32,130.409 ; 33.2@157.759,162.439 33.2@158.496,161.702
  Top Layer w0.5: v3(137.922,124.206) 144.17,124.206 146.634,126.67 146.634,128.626 147.904,129.896 v3(149.962,129.896)
  Top Layer w0.6: v3(156.134,139.141) 157.429,139.141 158.496,140.208 33.2@158.496,161.702
  Bottom Layer w0.5: v3(125.933,133.223) 129.565,129.591 129.565,126.187 131.547,124.206 v3(137.922,124.206)
  Bottom Layer w1: v3(149.962,129.896) 149.962,135.382 153.01,138.43 155.423,138.43 v3(156.134,139.141)
scl: 65.1 P1.3 P2.3 U3.57 | length 82.9
  Top Layer w0.25: U3.57@124.82,130.409 124.82,133.32 125.349,133.85 125.349,135.509
  Top Layer w0.4: v1@97.993,135.484 99.187,136.677 124.181,136.677 125.349,135.509
  Top Layer w0.5: P2.3@80.01,108.839 81.128,108.839 82.296,110.007 82.296,121.437 83.287,122.428 88.875,122.428 90.094,121.209 P1.3@92.989,121.209 ; v1(97.993,135.433) v1@97.993,135.484
  Bottom Layer w0.5: 65.1@87.954,120.853 65.1@88.31,121.209
  Bottom Layer w1: 65.1@88.31,121.209 P1.3@92.989,121.209 96.215,121.209 97.18,122.174 97.18,134.62 v1(97.993,135.433)
sda: 67.1 P1.4 P2.4 U3.59 | length 70.7
  Top Layer w0.25: U3.59@123.82,130.409 123.82,133.559
  Top Layer w0.35: 122.479,134.899 123.82,133.559
  Top Layer w0.5: P2.4@80.01,111.379 80.01,122.072 81.686,123.749 P1.4@92.989,123.749 ; 108.56,134.899 122.479,134.899
  Top Layer w0.7: 105.01,128.124 105.01,131.35 108.56,134.899
  Top Layer w1: P1.4@92.989,123.749 95.555,123.749 99.162,127.356 104.242,127.356 105.01,128.124
  Bottom Layer w1: 67.1@87.853,124.155 92.583,124.155 P1.4@92.989,123.749
VCC: 4.1 5.2 7.1 9.2 16.2 19.8 23.1 54.1@110.635,117.344 55.1@121.307,129.972 55.2@113.411,130.22 58.1 59.1 70.2 ams1.2 ams1.4 ca2.2 D1.2 P7.1 P8.1 U1.8 U3.13 U3.19 U3.32 U3.48 U3.64 U4.3 | length 430.2
  Top Layer w0.25: 111.862,171.45 111.912,171.399 ; v3(114.63,122.225) 114.63,122.453 114.666,122.489 U3.13@119.4,122.489 ; v1(123.876,125.095) 123.876,125.679 126.686,128.489 U3.48@130.74,128.489 ; U3.32@128.82,119.069 v1(129.241,119.069)
  Top Layer w0.3: U3.19@122.32,119.069 122.32,121.786 ; U3.32@128.82,119.069 v1@128.981,119.231
  Top Layer w0.35: 122.32,121.786 123.876,123.342
  Top Layer w0.5: v1(64.237,176.581) 65.329,177.673 69.799,177.673 75.463,172.009 84.379,172.009 ; 70.2@82.702,149.501 70.2@83.392,150.19 ; 87.071,173.787 87.681,173.177 91.643,173.177 92.287,172.534 D1.2@92.287,171.78 ; 88.544,176.555 v1(97.561,176.555) ; U1.8@102.419,172.999 v1(102.419,175.339) 102.777,174.981 v1(105.715,174.981) ; 102.565,100.889 102.565,110.16 v3(114.63,122.225) ; 123.876,123.342 v1(123.876,125.095) 125.146,123.825 127.864,123.825 128.981,122.707 v1@128.981,119.231
  Top Layer w0.6: v1(63.119,181.483) 61.214,181.483 59.588,183.109 59.588,213.233 61.341,214.986 75.032,214.986 v1@76.436,213.581
  Top Layer w0.7: 70.2@83.392,150.19 U4.3@86.58,150.19 88.697,150.19 ; 87.071,173.787 87.071,175.082 88.544,176.555 ; v1(149.377,143.713) 151.74,146.075
  Top Layer w0.8: 151.74,146.075 151.74,152.044
  Top Layer w0.9: 98.323,161.646 109.195,161.646 ; v1(148.336,155.448) 151.74,152.044
  Top Layer w1: 87.071,175.082 85.09,175.082 84.379,174.371 84.379,172.009 84.379,161.95 89.484,156.845 89.484,150.978 88.697,150.19 ; 4.1@91.313,95.07 92.006,95.762 ams1.4@99.873,95.762 ; 16.2@96.881,165.532 96.881,163.088 98.323,161.646 ; ams1.2@99.873,89.962 ams1.4@99.873,95.762 ; 102.565,100.889 99.873,98.196 ams1.4@99.873,95.762 ; v1(108.407,176.047) 111.912,172.542 111.912,171.399 111.912,164.363 109.195,161.646 ; v1(110.769,171.45) 111.862,171.45 ; v1(119.101,171.323) 119.101,161.722 120.828,159.995 124.638,159.995 128.168,156.464 132.563,156.464 134.417,158.318 134.417,162.357 137.287,165.227 144.202,165.227 9.2@145.11,164.318 ; v1(138.1,119.38) 138.278,119.558 v1(142.57,119.558) ; 9.2@145.463,164.214 147.015,162.662 v1(147.015,158.801)
  Bottom Layer w0.25: v1(149.377,143.713) 58.1@150.221,143.713
  Bottom Layer w0.5: ca2.2@73.736,212.221 74.977,213.462 v1(76.352,213.462) ; 55.2@113.665,129.896 113.665,130.353 114.529,131.216 119.837,131.216 v1(120.701,130.353) 120.701,127.432 123.038,125.095 v1(123.876,125.095) 123.876,123.419 122.682,122.225 v3(114.63,122.225) ; 59.1@150.171,141.046 59.1@150.221,141.097
  Bottom Layer w0.8: 59.1@150.221,141.097 58.1@150.221,143.713
  Bottom Layer w1: v1(63.119,181.483) 64.237,180.365 v1(64.237,176.581) ; 4.1@91.313,95.07 91.586,94.797 5.2@93.396,94.797 ; v1(97.561,176.555) 101.202,176.555 v1(102.419,175.339) 102.419,174.225 101.34,173.146 23.1@99.974,173.146 ; v1(105.715,174.981) 107.34,174.981 v1(108.407,176.047) ; v1(110.769,171.45) 110.896,171.323 v1(119.101,171.323) ; v1(129.241,119.069) 129.552,119.38 v1(138.1,119.38) ; v1(142.57,119.558) 145.009,119.558 147.142,117.424 P7.1@149.174,117.424 ; v1(147.015,158.801) 148.336,157.48 v1(148.336,155.448) ; 59.1@150.171,141.046 147.269,138.145 147.269,119.329 P7.1@149.174,117.424 ; P8.1@155.397,117.551 155.27,117.424 P7.1@149.174,117.424
pads on no net: 3.0 DZ1.0 DZ2.0 DZ3.0 P1.5 P1.6 P1.8 P1.9 P1.10 P3.6 P3.9 rele11.3 U2.3 U3.1 U3.28 U3.55 U3.56 U4.5

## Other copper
Top Layer:
  text "PAVANTECH.IR" at 82.575,213.716 h1.5
  text "PAVAN" at 86.665,211.125 h1.52
  text "09114764806" at 83.845,208.991 h1.3

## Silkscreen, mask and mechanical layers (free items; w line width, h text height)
Top Overlay:
  lines w0.2: 58.496,162.281 75.87,162.281 75.87,85.877 161.468,85.877 161.468,162.712 179.705,162.712 179.705,216.129 58.496,216.129 58.496,162.281
Bottom Overlay:
  text "+" at 105.004,178.13 h1.52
